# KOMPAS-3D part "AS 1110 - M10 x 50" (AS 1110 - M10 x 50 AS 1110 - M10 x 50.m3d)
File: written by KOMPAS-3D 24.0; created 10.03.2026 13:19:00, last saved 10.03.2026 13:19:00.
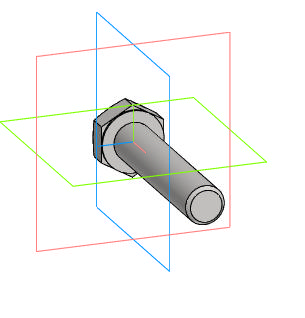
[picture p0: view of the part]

Document properties: Автор: R2D2; Полное имя файла: E:\Работа\Зайцев\BV3232P(4pc)-FP-3WL-F-ISO-H Кран шаровой DN.ru Ду15-100 Ру16\DN100\исходные материалы\AS 1110 - M10 x 50 AS 1110 - M10 x 50.m3d

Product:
- Body: Solid1  | qty 1
- Part/product: AS 1110 - M10 x 50
    Комментарий: Болты и винты   шестигранные точные   метрические ISO
    additional columns: Сталь, мягкая

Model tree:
1. Solid1  (labels: Solid1)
